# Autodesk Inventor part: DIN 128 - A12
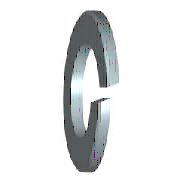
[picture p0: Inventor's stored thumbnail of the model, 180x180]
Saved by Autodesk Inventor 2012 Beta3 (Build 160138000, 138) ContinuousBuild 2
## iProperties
IsCustomPart: 0
Created: 2010-02
Part Number: DIN 128 - A12
Material: Steel, Mild
Description: Spring Washer
Document SubType Name: Modeling
Standard: DIN 128
Designer: Thom Tremblay
Standard Revision: 1994
Standards Organization: DIN
Language: en-US
Size Designation: A12
Categories: <MemberInstance><Categories><Category DisplayName="Fasteners" InternalName="e4da775c-781d-43d5-af7c-5136215cf5a6" Mnemonic="FSTN"><Category DisplayName="Washers
Density: 1 g/cm^3
Author: Thom Tremblay
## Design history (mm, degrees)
sketch "Sketch2"
  geometry: L1 (0, -6.35)-(0, 6.35) reference; L2 (2.1, 10.55)-(2.1, -10.55) reference; L3 (-1.2, 0)-(7.2, 0) reference; L4 (0, -0.42)-(2.1, 0.792); L5 (0, 0.42)-(2.1, 1.632)
  constraints: 4 end point, 4 point on line, 1 parallel
  dimensions: "d4" = 0.42 distance from line of L3 L4.start (= 0.2 x SD); "d5" = 0.42 distance from line of L3 L5.start (= 0.2 x SD); "d6" = 60 deg angle of L2 L4 (= FAWI)
extrude "Cut" cut sketch "Sketch2" stored distance "d7" = 2.1 (= SD); taper "d8" = 0 deg
workaxis "Work Axis1"
workplane "Work Plane1"
body "Solid1"
sketch "Sketch1"
  geometry: C1 r 10.55 at (0, 0); C2 r 6.35 at (0, 0); 1 further point
  constraints: 2 centre point, 2 coincident
  dimensions: "d0" = 12.7 diameter of C2 (= SD1); "d1" = 21.1 diameter of C1 (= SD2)
extrude "Body" new body sketch "Sketch1" distance "d2" = 2.1 (= SD); taper "d3" = 0 deg
fillet "Fillet" dims "d13" = 1 (= R)
other parameters: "SD1" = 12.7 [user parameter; used in 1 equation term], "SD2" = 21.1 [user parameter; used in 1 equation term], "SD" = 2.1 [user parameter; used in 4 equation terms], "FAWI" = 60 deg [user parameter; used in 1 equation term], "d9" = 0, "d10" = 0, "d11" = 0, "d12" = 0, "R" = 1 [user parameter; used in 1 equation term], "NND" = 12 [user parameter]
